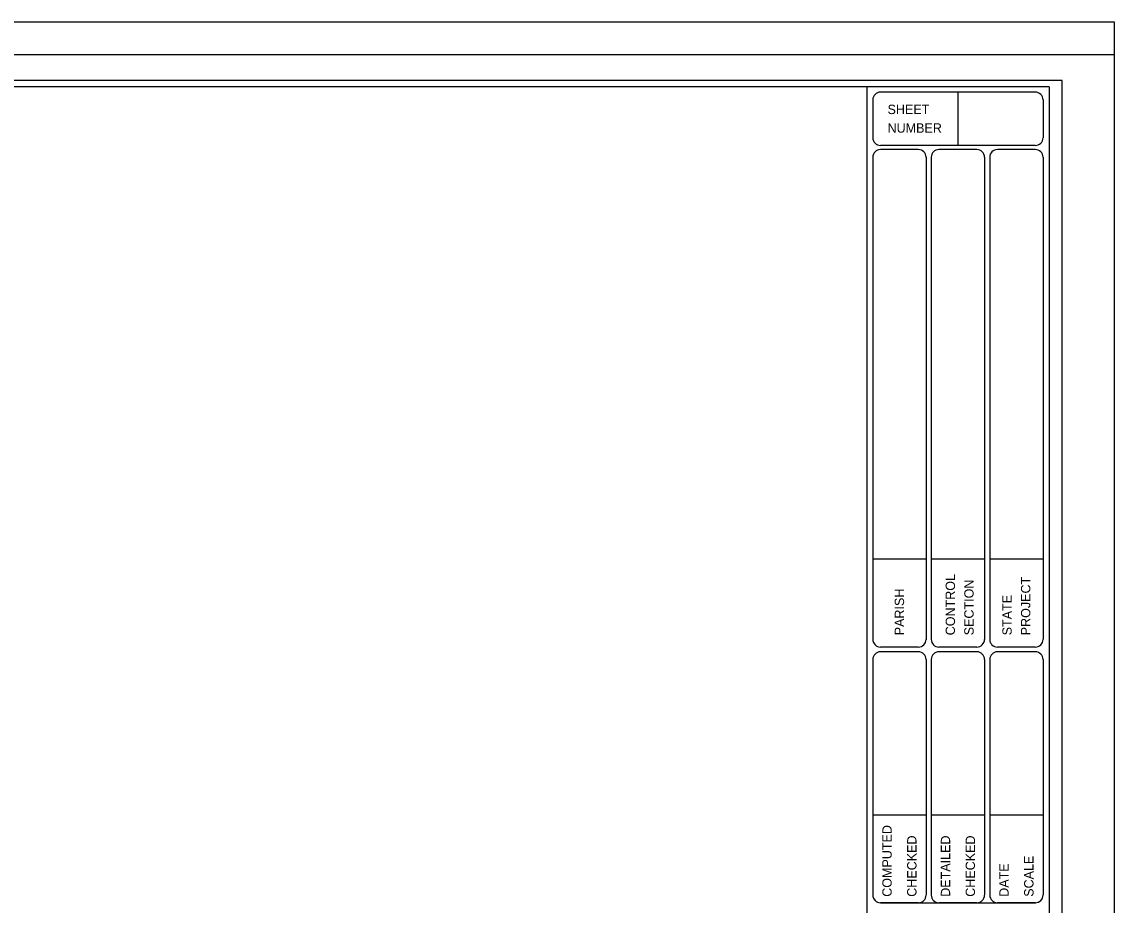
# Model space of a CAD drawing. Extents: x -2.5 to 31.7, y -0.7 to 21.7.
# Drawn here: x 23.31 to 31.7, y 14.72 to 21.5 of the extents above; entities that cross this region are included whole.
import ezdxf

# ---------------------------------------------------------------- set-up
doc = ezdxf.new("R2010")
doc.units = 0
for name, color, linetype in [('Plot Border', 7, 'Continuous'), ('Plot Border 2', 7, 'Continuous'), ('Sheet Border', 7, 'Continuous')]:
    doc.layers.add(name, color=color, linetype=linetype)

msp = doc.modelspace()

# ---------------------------------------------------------------- linework, layer by layer
at = {"layer": 'Plot Border'}
for points in [[(-2.3, 21.5), (31.7, 21.5), (31.7, -0.5), (-2.3, -0.5)], [(31.3, 21.05), (-1.7, 21.05), (-1.7, -0.05), (31.3, -0.05)]]:
    msp.add_lwpolyline(points, close=True, dxfattribs=at)
at = {"layer": 'Plot Border 2'}
msp.add_lwpolyline([(-2.3, 21.25), (31.7, 21.25), (31.7, -0.25), (-2.3, -0.25)], close=True, dxfattribs=at)
at = {"layer": 'Sheet Border'}
for p, q in [((31.2, 21), (-0.3, 21)), ((29.8, 21), (29.8, 0.262)), ((31.2, 21), (31.2, 0)), ((29.8462, 20.9009), (29.8462, 20.6107)), ((31.0944, 20.9604), (29.9057, 20.9604)), ((30.5, 20.9604), (30.5, 20.5513)), ((31.1538, 20.9009), (31.1538, 20.6107)), ((31.0944, 20.5513), (29.9057, 20.5513)), ((30.1959, 20.5196), (29.9057, 20.5196)), ((30.6451, 20.5196), (30.3544, 20.5196)), ((31.0944, 20.5196), (30.8036, 20.5196)), ((29.8462, 20.4641), (29.8462, 16.7544)), ((30.2554, 20.4646), (30.2554, 16.7539)), ((30.295, 20.4601), (30.295, 16.7589)), ((30.7046, 20.4606), (30.7046, 16.7579)), ((30.7442, 20.4601), (30.7442, 16.7589)), ((31.1538, 20.4601), (31.1538, 16.7589)), ((30.2554, 17.373), (29.8462, 17.373)), ((30.7046, 17.373), (30.295, 17.373)), ((31.1538, 17.373), (30.7442, 17.373)), ((30.1959, 16.6995), (29.9057, 16.6995)), ((30.6451, 16.6995), (30.3544, 16.6995)), ((31.0944, 16.6995), (30.8036, 16.6995)), ((30.1964, 16.6628), (29.9057, 16.6628)), ((30.6456, 16.6628), (30.3549, 16.6628)), ((31.0949, 16.6628), (30.8041, 16.6628)), ((29.8462, 16.6078), (29.8462, 14.7956)), ((30.2558, 16.6034), (30.2558, 14.7956)), ((30.2955, 16.6078), (30.2955, 14.7956)), ((30.7051, 16.6034), (30.7051, 14.7956)), ((30.7447, 16.6078), (30.7447, 14.7956)), ((31.1543, 16.6034), (31.1543, 14.7956)), ((30.2554, 15.4097), (29.8462, 15.4097)), ((30.7046, 15.4097), (30.295, 15.4097)), ((31.1538, 15.4097), (30.7442, 15.4097)), ((29.9057, 14.7365), (31.0944, 14.7365)), ((30.1964, 14.7361), (29.9057, 14.7361)), ((30.6456, 14.7361), (30.3549, 14.7361)), ((31.0949, 14.7361), (30.8041, 14.7361))]:
    msp.add_line(p, q, dxfattribs=at)
for centre, start, end in [((29.9055, 20.901), 90, 180), ((31.0942, 20.901), 0, 90), ((29.9055, 20.6105), 180, 270), ((31.0942, 20.6105), 270, 0), ((29.9055, 20.4599), 90, 180), ((30.1961, 20.4599), 0, 90), ((30.3546, 20.4599), 90, 180), ((30.6451, 20.4599), 0, 90), ((30.8036, 20.4599), 90, 180), ((31.0942, 20.4599), 0, 90), ((29.9055, 16.7587), 180, 270), ((30.1961, 16.7587), 270, 0), ((30.3546, 16.7587), 180, 270), ((30.6451, 16.7587), 270, 0), ((30.8036, 16.7587), 180, 270), ((31.0942, 16.7587), 270, 0), ((29.9055, 16.6036), 90, 180), ((30.1962, 16.6036), 0, 90), ((30.3547, 16.6036), 90, 180), ((30.6455, 16.6036), 0, 90), ((30.804, 16.6036), 90, 180), ((31.0947, 16.6036), 0, 90), ((29.9055, 14.796), 180, 270), ((29.9057, 14.7954), 180, 270), ((30.1962, 14.7954), 270, 0), ((30.3549, 14.7954), 180, 270), ((30.6455, 14.7954), 270, 0), ((30.8041, 14.7954), 180, 270), ((31.0942, 14.796), 270, 0), ((31.0947, 14.7954), 270, 0)]:
    msp.add_arc(centre, 0.0594, start, end, dxfattribs=at)

# ---------------------------------------------------------------- texts
for s, p in [('SHEET', (29.9597, 20.7919)), ('NUMBER', (29.9597, 20.6488))]:
    msp.add_text(s, height=0.072, dxfattribs=at).set_placement(p)
for s, p in [('CONTROL', (30.4778, 16.7896)), ('SECTION', (30.621, 16.7896)), ('PROJECT', (31.0563, 16.7896)), ('PARISH', (30.0866, 16.7896)), ('STATE', (30.9132, 16.7896)), ('COMPUTED', (29.9915, 14.7818)), ('CHECKED', (30.1821, 14.7818)), ('DETAILED', (30.4407, 14.7818)), ('CHECKED', (30.6314, 14.7818)), ('DATE', (30.8899, 14.7818)), ('SCALE', (31.0806, 14.7818))]:
    msp.add_text(s, height=0.072, rotation=90, dxfattribs=at).set_placement(p)

doc.saveas('drawing.dxf')
